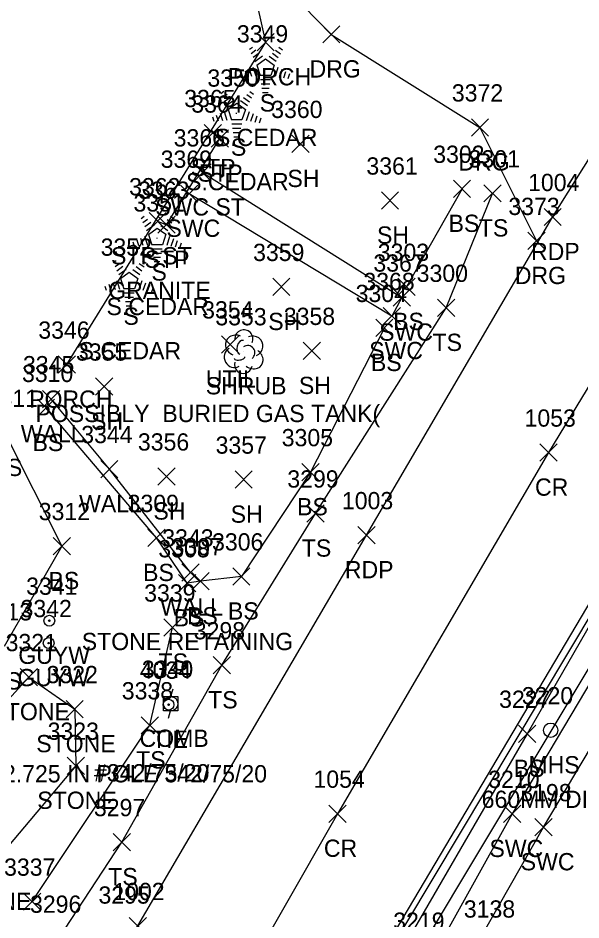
# Model space of a CAD drawing. Extents: x 1634209 to 1639641, y 608564 to 612258.
# Drawn here: x 1638888.9 to 1638954.2, y 610938 to 611042.5 of the extents above; entities that cross this region are included whole.
import ezdxf

# ---------------------------------------------------------------- set-up
doc = ezdxf.new("R2010")
doc.units = 0
for name, color, linetype in [('C_A', 7, 'Continuous'), ('C_C', 7, 'Continuous'), ('C_I', 7, 'Continuous'), ('CBP', 7, 'Continuous'), ('DCP', 7, 'Continuous'), ('L_A', 7, 'Continuous'), ('L_C', 7, 'Continuous'), ('L_I', 7, 'Continuous'), ('L_TIC', 7, 'Continuous'), ('LASF', 7, 'Continuous'), ('LBF', 7, 'Continuous'), ('LELB', 7, 'Continuous'), ('LSH', 7, 'Continuous'), ('LTC', 7, 'Continuous'), ('LW', 7, 'Continuous'), ('P_A', 7, 'Continuous'), ('P_I', 7, 'Continuous'), ('P_TIC', 7, 'Continuous'), ('PET', 7, 'Continuous'), ('PRC', 7, 'Continuous'), ('R_A', 7, 'Continuous'), ('R_I', 7, 'Continuous'), ('R_TIC', 7, 'Continuous'), ('RDG', 7, 'Continuous'), ('RSW', 7, 'Continuous'), ('U_A', 7, 'Continuous'), ('U_C', 7, 'Continuous'), ('U_I', 7, 'Continuous'), ('UDEFAULT', 7, 'Continuous'), ('UP', 7, 'Continuous'), ('UPGW', 7, 'Continuous'), ('USMH', 7, 'Continuous')]:
    doc.layers.add(name, color=color, linetype=linetype)

msp = doc.modelspace()

# ---------------------------------------------------------------- linework, layer by layer
at = {"layer": 'CBP'}
for radius in [0.625, 0.0833]:
    msp.add_circle((1638906.38, 610962.92), radius, dxfattribs=at)
at = {"layer": 'DCP'}
msp.add_lwpolyline([(1638930.73, 610932.22), (1638981.11, 611016.29)], dxfattribs=at)
at = {"layer": 'L_TIC'}
for points in [[(1638916.64, 611038.67), (1638918.64, 611040.67)], [(1638918.64, 611038.67), (1638916.64, 611040.67)], [(1638910.5, 611028.15), (1638912.5, 611030.15)], [(1638912.5, 611028.15), (1638910.5, 611030.15)], [(1638911.32, 611027.51), (1638913.32, 611029.51)], [(1638913.32, 611027.51), (1638911.32, 611029.51)], [(1638920.67, 611026.89), (1638922.67, 611028.89)], [(1638922.67, 611026.89), (1638920.67, 611028.89)], [(1638939.41, 611021.69), (1638941.41, 611023.69)], [(1638941.41, 611021.69), (1638939.41, 611023.69)], [(1638942.95, 611021.16), (1638944.95, 611023.16)], [(1638944.95, 611021.16), (1638942.95, 611023.16)], [(1638931.06, 611020.33), (1638933.06, 611022.33)], [(1638933.06, 611020.33), (1638931.06, 611022.33)], [(1638904.11, 611017.93), (1638906.11, 611019.93)], [(1638906.11, 611017.93), (1638904.11, 611019.93)], [(1638905.15, 611017.53), (1638907.15, 611019.53)], [(1638907.15, 611017.53), (1638905.15, 611019.53)], [(1638918.45, 611010.32), (1638920.45, 611012.32)], [(1638920.45, 611010.32), (1638918.45, 611012.32)], [(1638932.98, 611010.33), (1638934.98, 611012.33)], [(1638934.98, 611010.33), (1638932.98, 611012.33)], [(1638937.58, 611007.9), (1638939.58, 611009.9)], [(1638939.58, 611007.9), (1638937.58, 611009.9)], [(1638930.4, 611005.57), (1638932.4, 611007.57)], [(1638932.4, 611005.57), (1638930.4, 611007.57)], [(1638922, 611002.91), (1638924, 611004.91)], [(1638924, 611002.91), (1638922, 611004.91)], [(1638893.59, 611001.32), (1638895.59, 611003.32)], [(1638895.59, 611001.32), (1638893.59, 611003.32)], [(1638897.9, 610998.78), (1638899.9, 611000.78)], [(1638899.9, 610998.78), (1638897.9, 611000.78)], [(1638891.75, 610997.31), (1638893.75, 610999.31)], [(1638893.75, 610997.31), (1638891.75, 610999.31)], [(1638891.16, 610996.3), (1638893.16, 610998.3)], [(1638893.16, 610996.3), (1638891.16, 610998.3)], [(1638898.51, 610989.22), (1638900.51, 610991.22)], [(1638900.51, 610989.22), (1638898.51, 610991.22)], [(1638921.83, 610988.86), (1638923.83, 610990.86)], [(1638923.83, 610988.86), (1638921.83, 610990.86)], [(1638905.13, 610988.36), (1638907.13, 610990.36)], [(1638907.13, 610988.36), (1638905.13, 610990.36)], [(1638914.09, 610988), (1638916.09, 610990)], [(1638916.09, 610988), (1638914.09, 610990)], [(1638922.42, 610984.07), (1638924.42, 610986.07)], [(1638924.42, 610984.07), (1638922.42, 610986.07)], [(1638903.97, 610981.24), (1638905.97, 610983.24)], [(1638905.97, 610981.24), (1638903.97, 610983.24)], [(1638893.01, 610980.3), (1638895.01, 610982.3)], [(1638895.01, 610980.3), (1638893.01, 610982.3)], [(1638907.91, 610977.24), (1638909.91, 610979.24)], [(1638909.91, 610977.24), (1638907.91, 610979.24)], [(1638909.07, 610976.22), (1638911.07, 610978.22)], [(1638911.07, 610976.22), (1638909.07, 610978.22)], [(1638913.82, 610976.78), (1638915.82, 610978.78)], [(1638915.82, 610976.78), (1638913.82, 610978.78)], [(1638907.53, 610975.99), (1638909.53, 610977.99)], [(1638909.53, 610975.99), (1638907.53, 610977.99)], [(1638905.82, 610970.86), (1638907.82, 610972.86)], [(1638907.82, 610970.86), (1638905.82, 610972.86)], [(1638911.56, 610966.49), (1638913.56, 610968.49)], [(1638913.56, 610966.49), (1638911.56, 610968.49)], [(1638889.17, 610965.12), (1638891.17, 610967.12)], [(1638891.17, 610965.12), (1638889.17, 610967.12)], [(1638894.49, 610961.41), (1638896.49, 610963.41)], [(1638896.49, 610961.41), (1638894.49, 610963.41)], [(1638903.21, 610959.53), (1638905.21, 610961.53)], [(1638905.21, 610959.53), (1638903.21, 610961.53)], [(1638946.97, 610958.55), (1638948.97, 610960.55)], [(1638948.97, 610958.55), (1638946.97, 610960.55)], [(1638894.61, 610954.85), (1638896.61, 610956.85)], [(1638896.61, 610954.85), (1638894.61, 610956.85)], [(1638899.97, 610946), (1638901.97, 610948)], [(1638901.97, 610946), (1638899.97, 610948)], [(1638889.56, 610939.1), (1638891.56, 610941.1)], [(1638891.56, 610939.1), (1638889.56, 610941.1)]]:
    msp.add_lwpolyline(points, dxfattribs=at)
at = {"layer": 'LASF'}
msp.add_lwpolyline([(1638882.52, 610952.4), (1638880.6, 610955.65), (1638890.17, 610966.12), (1638895.49, 610962.41), (1638895.61, 610955.85), (1638885.71, 610944.15), (1638879.84, 610948.64)], dxfattribs=at)
at = {"layer": 'LBF'}
for points in [[(1638894.59, 611002.32), (1638917.64, 611039.67), (1638915.8, 611047.97)], [(1638905.11, 611018.93), (1638906.15, 611018.53), (1638912.32, 611028.51), (1638911.5, 611029.15)]]:
    msp.add_lwpolyline(points, dxfattribs=at)
at = {"layer": 'LELB'}
for points in [[(1638893.63, 610935.81), (1638900.97, 610947), (1638912.56, 610967.49), (1638923.42, 610985.07), (1638938.58, 611008.9), (1638943.95, 611022.16)], [(1638940.41, 611022.69), (1638933.98, 611011.33)], [(1638980.31, 611015.48), (1638967.73, 610993.79), (1638947.97, 610959.55), (1638931.37, 610930.97), (1638912.43, 610898.55), (1638893.71, 610864.41), (1638879.66, 610839.16)], [(1638931.4, 611006.57), (1638922.83, 610989.86), (1638914.82, 610977.78), (1638910.07, 610977.22), (1638908.53, 610976.99), (1638904.97, 610982.24), (1638892.16, 610997.3)], [(1638887.4, 610994.41), (1638894.01, 610981.3), (1638887.3, 610969.68), (1638874.48, 610974.16)], [(1638882.82, 610837.01), (1638905.5, 610879.25), (1638921.2, 610907.42), (1638935.13, 610933.84), (1638959.96, 610975.17)], [(1638890.56, 610940.1), (1638904.21, 610960.53), (1638906.82, 610971.86)]]:
    msp.add_lwpolyline(points, dxfattribs=at)
at = {"layer": 'LSH'}
msp.add_line((1638915.06, 611003.87), (1638915.06, 611003.87), dxfattribs=at)
msp.add_line((1638915.06, 611003.87), (1638915.06, 611003.87), dxfattribs=at)
msp.add_arc((1638915.11, 611005.3), 1.05, 335.5272, 180.9563, dxfattribs=at)
for centre, major_axis, ratio, start_param, end_param in [((1638914.27, 611004.54), (1.21, -0.51), 0.895232, 1.570796, 4.712389), ((1638916.1, 611004.45), (-1.14, -0.48), 0.949671, 1.570796, 4.712389), ((1638914.85, 611004.33), (-0.208, -0.792), 0.645439, 3.141593, 6.283185), ((1638915.56, 611003.7), (-0.5, 0.667), 0.989748, 3.141593, 6.283185), ((1638913.98, 611003.16), (0.58, -1.04), 0.959034, 3.141593, 6.283185), ((1638916.06, 611003.04), (-1.09, 0.79), 0.841452, 1.570796, 4.712389), ((1638915.06, 611002.37), (0.26, 1.06), 0.942809, 1.570796, 4.712389), ((1638914.6, 611003.12), (-0.625, -0.083), 0.423636, 0, 3.141593)]:
    msp.add_ellipse(centre, major_axis=major_axis, ratio=ratio, start_param=start_param, end_param=end_param, dxfattribs=at)
at = {"layer": 'LTC'}
for p, q in [((1638915.76, 611038.85), (1638916.12, 611039.11)), ((1638915.97, 611038.38), (1638916.5, 611038.77)), ((1638919.16, 611039.09), (1638919.58, 611038.79)), ((1638916.18, 611037.92), (1638916.89, 611038.43)), ((1638916.39, 611037.45), (1638917.27, 611038.09)), ((1638916.62, 611037), (1638917.63, 611037.73)), ((1638917.63, 611037.73), (1638918.62, 611037.01)), ((1638918.05, 611038.05), (1638918.86, 611037.46)), ((1638918.42, 611038.39), (1638919.1, 611037.9)), ((1638918.79, 611038.74), (1638919.34, 611038.34)), ((1638916.16, 611036.78), (1638916.49, 611035.76)), ((1638916.62, 611037), (1638917, 611035.8)), ((1638918.62, 611037.01), (1638918.23, 611035.8)), ((1638919.06, 611036.74), (1638918.72, 611035.7)), ((1638914.8, 611036.13), (1638914.95, 611035.66)), ((1638915.25, 611036.35), (1638915.46, 611035.69)), ((1638915.71, 611036.56), (1638915.98, 611035.73)), ((1638918.23, 611035.8), (1638917, 611035.8)), ((1638919.51, 611036.49), (1638919.22, 611035.6)), ((1638919.95, 611036.24), (1638919.71, 611035.51)), ((1638920.4, 611035.99), (1638920.21, 611035.41)), ((1638918.2, 611035.3), (1638917.05, 611035.3)), ((1638918.11, 611034.8), (1638917.12, 611034.8)), ((1638912.42, 611033.73), (1638912.78, 611033.98)), ((1638912.63, 611033.26), (1638913.16, 611033.65)), ((1638915.45, 611033.62), (1638916, 611033.22)), ((1638915.82, 611033.97), (1638916.24, 611033.66)), ((1638918.03, 611034.3), (1638917.2, 611034.3)), ((1638917.94, 611033.8), (1638917.27, 611033.8)), ((1638912.84, 611032.8), (1638913.55, 611033.31)), ((1638913.05, 611032.33), (1638913.93, 611032.97)), ((1638913.28, 611031.87), (1638914.29, 611032.61)), ((1638914.29, 611032.61), (1638915.28, 611031.88)), ((1638914.71, 611032.92), (1638915.52, 611032.33)), ((1638915.08, 611033.27), (1638915.76, 611032.78)), ((1638912.82, 611031.66), (1638913.15, 611030.64)), ((1638913.28, 611031.87), (1638913.66, 611030.68)), ((1638915.28, 611031.88), (1638914.89, 611030.68)), ((1638915.72, 611031.61), (1638915.38, 611030.57)), ((1638911.46, 611031.01), (1638911.61, 611030.54)), ((1638911.91, 611031.22), (1638912.12, 611030.57)), ((1638912.37, 611031.44), (1638912.64, 611030.6)), ((1638914.89, 611030.68), (1638913.66, 611030.68)), ((1638916.17, 611031.36), (1638915.88, 611030.48)), ((1638916.61, 611031.11), (1638916.37, 611030.38)), ((1638917.06, 611030.86), (1638916.87, 611030.29)), ((1638914.86, 611030.18), (1638913.71, 611030.18)), ((1638914.77, 611029.68), (1638913.78, 611029.68)), ((1638914.69, 611029.18), (1638913.86, 611029.18)), ((1638914.6, 611028.68), (1638913.93, 611028.68)), ((1638903.2, 611019.26), (1638903.55, 611019.52)), ((1638903.41, 611018.79), (1638903.94, 611019.18)), ((1638906.23, 611019.15), (1638906.77, 611018.75)), ((1638906.6, 611019.5), (1638907.02, 611019.2)), ((1638903.62, 611018.33), (1638904.32, 611018.84)), ((1638903.83, 611017.86), (1638904.71, 611018.5)), ((1638904.05, 611017.41), (1638905.06, 611018.14)), ((1638905.06, 611018.14), (1638906.06, 611017.42)), ((1638905.48, 611018.45), (1638906.29, 611017.87)), ((1638905.85, 611018.8), (1638906.53, 611018.31)), ((1638903.14, 611016.97), (1638903.41, 611016.14)), ((1638903.6, 611017.19), (1638903.93, 611016.17)), ((1638904.05, 611017.41), (1638904.44, 611016.21)), ((1638906.06, 611017.42), (1638905.67, 611016.21)), ((1638906.5, 611017.15), (1638906.16, 611016.11)), ((1638906.94, 611016.9), (1638906.65, 611016.01)), ((1638902.23, 611016.54), (1638902.38, 611016.07)), ((1638902.69, 611016.76), (1638902.9, 611016.1)), ((1638905.67, 611016.21), (1638904.44, 611016.21)), ((1638907.39, 611016.65), (1638907.15, 611015.92)), ((1638907.83, 611016.4), (1638907.64, 611015.82)), ((1638905.63, 611015.71), (1638904.49, 611015.71)), ((1638905.55, 611015.21), (1638904.56, 611015.21)), ((1638899.96, 611014.14), (1638900.31, 611014.39)), ((1638900.17, 611013.67), (1638900.7, 611014.05)), ((1638900.38, 611013.2), (1638901.08, 611013.72)), ((1638902.98, 611014.03), (1638903.53, 611013.63)), ((1638903.36, 611014.38), (1638903.77, 611014.07)), ((1638905.46, 611014.71), (1638904.63, 611014.71)), ((1638905.38, 611014.21), (1638904.7, 611014.21)), ((1638900.59, 611012.74), (1638901.46, 611013.38)), ((1638900.81, 611012.28), (1638901.82, 611013.02)), ((1638901.82, 611013.02), (1638902.82, 611012.29)), ((1638902.24, 611013.33), (1638903.05, 611012.74)), ((1638902.61, 611013.68), (1638903.29, 611013.19)), ((1638899.45, 611011.63), (1638899.66, 611010.98)), ((1638899.9, 611011.85), (1638900.17, 611011.01)), ((1638900.36, 611012.06), (1638900.69, 611011.05)), ((1638900.81, 611012.28), (1638901.2, 611011.09)), ((1638902.82, 611012.29), (1638902.43, 611011.09)), ((1638903.26, 611012.02), (1638902.92, 611010.98)), ((1638903.7, 611011.77), (1638903.41, 611010.89)), ((1638898.99, 611011.41), (1638899.14, 611010.95)), ((1638902.43, 611011.09), (1638901.2, 611011.09)), ((1638902.39, 611010.59), (1638901.25, 611010.59)), ((1638904.15, 611011.52), (1638903.91, 611010.79)), ((1638904.59, 611011.27), (1638904.4, 611010.7)), ((1638902.31, 611010.09), (1638901.32, 611010.09)), ((1638902.22, 611009.59), (1638901.39, 611009.59)), ((1638902.14, 611009.09), (1638901.46, 611009.09))]:
    msp.add_line(p, q, dxfattribs=at)
at = {"layer": 'LW'}
msp.add_lwpolyline([(1638908.91, 610978.24), (1638899.51, 610990.22), (1638892.75, 610998.31)], dxfattribs=at)
at = {"layer": 'P_TIC'}
for points in [[(1638949.92, 611018.42), (1638951.92, 611020.42)], [(1638951.92, 611018.42), (1638949.92, 611020.42)], [(1638949.44, 610991.13), (1638951.44, 610993.13)], [(1638951.44, 610991.13), (1638949.44, 610993.13)], [(1638928.33, 610981.56), (1638930.33, 610983.56)], [(1638930.33, 610981.56), (1638928.33, 610983.56)], [(1638924.96, 610949.29), (1638926.96, 610951.29)], [(1638926.96, 610949.29), (1638924.96, 610951.29)], [(1638901.82, 610936.28), (1638903.82, 610938.28)], [(1638903.82, 610936.28), (1638901.82, 610938.28)]]:
    msp.add_lwpolyline(points, dxfattribs=at)
at = {"layer": 'PET'}
for points in [[(1638854.83, 610853.22), (1638885.37, 610909), (1638902.82, 610937.28), (1638929.33, 610982.56), (1638950.92, 611019.42), (1638971.29, 611051.92), (1639000.04, 611096.96), (1639023.57, 611133.7), (1639039.12, 611159.19), (1639064.62, 611197.78), (1639080.51, 611223.3), (1639114.23, 611277.34), (1639131.17, 611302.28), (1639149.64, 611331.79), (1639176.42, 611372.35), (1639193.48, 611398.88), (1639220.96, 611441.47), (1639247.22, 611483.75)], [(1638878.4, 610839.82), (1638902.26, 610883.1), (1638925.76, 610925.06), (1638957.25, 610978.12), (1638978.73, 611014.12), (1639004.29, 611055.32), (1639040.97, 611112.28), (1639073.41, 611162.89), (1639072.72, 611163.46), (1639102.57, 611207.56), (1639124.27, 611240.99), (1639140.69, 611264.29), (1639156.2, 611287.4), (1639175.63, 611318.1), (1639189.77, 611341.61), (1639219.88, 611389.38), (1639245.26, 611428.04), (1639265.27, 611462.65)]]:
    msp.add_lwpolyline(points, dxfattribs=at)
at = {"layer": 'PRC'}
msp.add_lwpolyline([(1639250.46, 611462.84), (1639222.36, 611418.18), (1639195.34, 611376.28), (1639169.71, 611336.75), (1639147.17, 611302.78), (1639120.59, 611261.16), (1639092.55, 611217.83), (1639063.71, 611172.41), (1639032.46, 611123.7), (1639004.79, 611080.3), (1638977.88, 611037.27), (1638950.44, 610992.13), (1638925.96, 610950.29), (1638900.29, 610905.36), (1638879.75, 610869.2), (1638867.15, 610846.08)], dxfattribs=at)
at = {"layer": 'R_TIC'}
for points in [[(1638924.25, 611039.58), (1638926.25, 611041.58)], [(1638926.25, 611039.58), (1638924.25, 611041.58)], [(1638941.49, 611028.8), (1638943.49, 611030.8)], [(1638943.49, 611028.8), (1638941.49, 611030.8)], [(1638909.33, 611023.59), (1638911.33, 611025.59)], [(1638911.33, 611023.59), (1638909.33, 611025.59)], [(1638907.77, 611021.12), (1638909.77, 611023.12)], [(1638909.77, 611021.12), (1638907.77, 611023.12)], [(1638948.04, 611015.65), (1638950.04, 611017.65)], [(1638950.04, 611015.65), (1638948.04, 611017.65)], [(1638932.43, 611009.09), (1638934.43, 611011.09)], [(1638934.43, 611009.09), (1638932.43, 611011.09)], [(1638931.28, 611006.95), (1638933.28, 611008.95)], [(1638933.28, 611006.95), (1638931.28, 611008.95)], [(1638945.23, 610949.27), (1638947.23, 610951.27)], [(1638947.23, 610949.27), (1638945.23, 610951.27)], [(1638948.86, 610947.73), (1638950.86, 610949.73)], [(1638950.86, 610947.73), (1638948.86, 610949.73)]]:
    msp.add_lwpolyline(points, dxfattribs=at)
at = {"layer": 'RDG'}
msp.add_lwpolyline([(1638917.17, 611048.87), (1638925.25, 611040.58), (1638942.49, 611029.8), (1638949.04, 611016.65)], dxfattribs=at)
at = {"layer": 'RSW'}
for points in [[(1639042.52, 611106.87), (1639016.95, 611067.31), (1638996.03, 611033.02), (1638978.68, 611004.78), (1638963.33, 610979.05), (1638946.23, 610950.27), (1638931.64, 610924.09), (1638919.4, 610902.22), (1638904.83, 610875.98), (1638895.3, 610858.44), (1638883.54, 610836.57)], [(1638887.24, 610836.54), (1638902.8, 610864.3), (1638908.08, 610874.62), (1638910.81, 610879.12), (1638923.92, 610902.1), (1638938.05, 610928.02), (1638949.86, 610948.73), (1638968.01, 610979.25), (1638983.29, 611004.79), (1638997.34, 611027.92), (1639015.73, 611058.3), (1639044.74, 611103.21)], [(1638910.33, 611024.59), (1638933.43, 611010.09), (1638932.28, 611007.95), (1638908.77, 611022.12)]]:
    msp.add_lwpolyline(points, dxfattribs=at)
at = {"layer": 'UDEFAULT'}
for points in [[(1638912.53, 611003.66), (1638914.53, 611005.66)], [(1638914.53, 611003.66), (1638912.53, 611005.66)]]:
    msp.add_lwpolyline(points, dxfattribs=at)
at = {"layer": 'UP'}
for p, q in [((1638906.87, 610964.7), (1638906.62, 610963.87)), ((1638905.79, 610962.2), (1638905.79, 610963.87)), ((1638905.79, 610963.87), (1638907.46, 610963.87)), ((1638907.46, 610963.87), (1638907.46, 610962.2)), ((1638906.62, 610963.03), (1638906.62, 610963.03)), ((1638907.46, 610962.2), (1638905.79, 610962.2)), ((1638906.37, 610961.37), (1638906.62, 610962.2))]:
    msp.add_line(p, q, dxfattribs=at)
msp.add_circle((1638906.62, 610963.03), 0.833, dxfattribs=at)
at = {"layer": 'UPGW'}
for centre, radius in [((1638892.55, 610972.65), 0.625), ((1638892.55, 610972.65), 0.0833), ((1638892.47, 610970.06), 0.625), ((1638892.47, 610970.06), 0.0833)]:
    msp.add_circle(centre, radius, dxfattribs=at)
at = {"layer": 'USMH'}
for p, q in [((1638950.69, 610959.96), (1638950.69, 610959.96)), ((1638951.53, 610959.96), (1638951.53, 610959.96))]:
    msp.add_line(p, q, dxfattribs=at)
msp.add_circle((1638950.69, 610959.96), 0.833, dxfattribs=at)

# ---------------------------------------------------------------- texts
at = {"layer": 'C_A'}
msp.add_text('TIE', height=2, dxfattribs=at).set_placement((1638904.46, 610957.92))
at = {"layer": 'C_C'}
msp.add_text('32.725 IN POLE 342/75/20', height=2, dxfattribs=at).set_placement((1638885.68, 610953.92))
at = {"layer": 'C_I'}
msp.add_text('4034', height=2, dxfattribs=at).set_placement((1638903.04, 610965.92))
at = {"layer": 'L_A'}
for s, p in [('PORCH', (1638913.26, 611034.67)), ('S', (1638916.95, 611031.64)), ('S', (1638913.61, 611026.52)), ('STP', (1638908.95, 611024.15)), ('STP', (1638909.77, 611023.51)), ('SH', (1638920.16, 611022.89)), ('BS', (1638938.85, 611017.69)), ('TS', (1638942.36, 611017.16)), ('SH', (1638930.55, 611016.33)), ('STP ST', (1638899.7, 611013.93)), ('STP', (1638903.6, 611013.53)), ('S', (1638904.39, 611012.05)), ('S', (1638901.15, 611006.93)), ('SH', (1638917.94, 611006.32)), ('BS', (1638932.42, 611006.33)), ('TS', (1638936.99, 611003.9)), ('BS', (1638929.84, 611001.57)), ('SHRUB', (1638910.69, 610998.87)), ('SH', (1638921.49, 610998.91)), ('PORCH', (1638890.21, 610997.32)), ('SH', (1638897.39, 610994.78)), ('WALL', (1638889.24, 610993.31)), ('BS', (1638890.6, 610992.3)), ('BS', (1638885.84, 610989.41)), ('WALL', (1638896, 610985.22)), ('BS', (1638921.28, 610984.86)), ('SH', (1638904.62, 610984.36)), ('SH', (1638913.58, 610984)), ('TS', (1638921.83, 610980.07)), ('BS', (1638903.42, 610977.24)), ('BS', (1638892.45, 610976.3)), ('WALL', (1638905.4, 610973.24)), ('BS', (1638906.97, 610971.99)), ('BS', (1638908.51, 610972.22)), ('BS', (1638913.26, 610972.78)), ('TS', (1638905.22, 610966.86)), ('BS', (1638885.74, 610964.68)), ('TS', (1638910.97, 610962.49)), ('STONE', (1638885.72, 610961.12)), ('STONE', (1638891.03, 610957.41)), ('TS', (1638902.62, 610955.53)), ('BS', (1638946.41, 610954.55)), ('STONE', (1638891.15, 610950.85)), ('TS', (1638899.38, 610942)), ('STONE', (1638881.25, 610939.15))]:
    msp.add_text(s, height=2, dxfattribs=at).set_placement(p)
at = {"layer": 'L_C'}
for s, p in [('S.CEDAR', (1638911.75, 611027.64)), ('S.CEDAR', (1638908.41, 611022.52)), ('GRANITE', (1638899.38, 611009.93)), ('S.CEDAR', (1638899.18, 611008.05)), ('S.CEDAR', (1638895.94, 611002.93)), ('STONE RETAINING', (1638896.31, 610969.24))]:
    msp.add_text(s, height=2, dxfattribs=at).set_placement(p)
at = {"layer": 'L_I'}
for s, p in [('3349', (1638914.3, 611039.64)), ('3350', (1638910.88, 611034.52)), ('3365', (1638908.19, 611032.15)), ('3364', (1638909.01, 611031.51)), ('3360', (1638918.28, 611030.89)), ('3302', (1638937.07, 611025.69)), ('3361', (1638929.32, 611024.33)), ('3301', (1638941.18, 611025.16)), ('3362', (1638901.8, 611021.93)), ('3363', (1638902.84, 611021.53)), ('3351', (1638902.31, 611020.05)), ('3352', (1638898.5, 611014.93)), ('3359', (1638916.18, 611014.32)), ('3303', (1638930.64, 611014.33)), ('3300', (1638935.15, 611011.9)), ('3304', (1638928.07, 611009.57)), ('3353', (1638911.8, 611006.87)), ('3358', (1638919.74, 611006.91)), ('3346', (1638891.27, 611005.32)), ('3355', (1638895.64, 611002.78)), ('3345', (1638889.49, 611001.31)), ('3310', (1638889.38, 611000.3)), ('3311', (1638885.28, 610997.41)), ('3344', (1638896.25, 610993.22)), ('3305', (1638919.5, 610992.86)), ('3356', (1638902.82, 610992.36)), ('3357', (1638911.83, 610992)), ('3299', (1638920.15, 610988.07)), ('3309', (1638901.63, 610985.24)), ('3312', (1638891.32, 610984.3)), ('3343', (1638905.65, 610981.24)), ('3306', (1638911.42, 610980.78)), ('3308', (1638905.19, 610979.99)), ('3307', (1638906.73, 610980.22)), ('3339', (1638903.55, 610974.86)), ('3313', (1638884.6, 610972.68)), ('3298', (1638909.3, 610970.49)), ('3321', (1638887.48, 610969.12)), ('3322', (1638892.23, 610965.41)), ('3338', (1638900.95, 610963.53)), ('3227', (1638944.71, 610962.55)), ('3323', (1638892.35, 610958.85)), ('3297', (1638897.72, 610950)), ('3337', (1638887.3, 610943.1)), ('3296', (1638890.31, 610938.81)), ('3219', (1638932.43, 610936.84))]:
    msp.add_text(s, height=2, dxfattribs=at).set_placement(p)
at = {"layer": 'LTC'}
for p in [(1638917.51, 611036.75), (1638914.17, 611031.62), (1638904.95, 611017.16), (1638901.7, 611012.03)]:
    msp.add_text('.', height=1.04, rotation=270, dxfattribs=at).set_placement(p)
at = {"layer": 'P_A'}
for s, p in [('RDP', (1638948.41, 611014.42)), ('CR', (1638948.87, 610987.13)), ('RDP', (1638926.82, 610977.56)), ('CR', (1638924.39, 610945.29))]:
    msp.add_text(s, height=2, dxfattribs=at).set_placement(p)
at = {"layer": 'P_I'}
for s, p in [('1004', (1638948.07, 611022.42)), ('1053', (1638947.66, 610995.13)), ('1003', (1638926.48, 610985.56)), ('1054', (1638923.18, 610953.29)), ('1002', (1638899.97, 610940.28))]:
    msp.add_text(s, height=2, dxfattribs=at).set_placement(p)
at = {"layer": 'R_A'}
for s, p in [('DRG', (1638922.73, 611035.58)), ('DRG', (1638939.98, 611024.8)), ('SWC ST', (1638904.83, 611019.59)), ('SWC', (1638906.13, 611017.12)), ('DRG', (1638946.53, 611011.65)), ('SWC', (1638930.8, 611005.09)), ('SWC', (1638929.64, 611002.95)), ('SWC', (1638943.59, 610945.27)), ('SWC', (1638947.22, 610943.73))]:
    msp.add_text(s, height=2, dxfattribs=at).set_placement(p)
at = {"layer": 'R_I'}
for s, p in [('3372', (1638939.23, 611032.8)), ('3366', (1638906.97, 611027.59)), ('3369', (1638905.46, 611025.12)), ('3373', (1638945.78, 611019.65)), ('3367', (1638930.13, 611013.09)), ('3368', (1638928.97, 611010.95)), ('3210', (1638943.45, 610953.27)), ('3198', (1638947.17, 610951.73)), ('3295', (1638898.25, 610939.87)), ('3138', (1638940.62, 610938.25))]:
    msp.add_text(s, height=2, dxfattribs=at).set_placement(p)
at = {"layer": 'U_A'}
for s, p in [('UTIL', (1638910.7, 610999.66)), ('GUYW', (1638888.95, 610967.65)), ('GUYW', (1638888.86, 610965.06)), ('COMB', (1638903.01, 610958.03)), ('MHS', (1638948.11, 610954.96))]:
    msp.add_text(s, height=2, dxfattribs=at).set_placement(p)
at = {"layer": 'U_C'}
for s, p in [('POSSIBLY  BURIED GAS TANK(', (1638890.94, 610995.66)), ('#342/75/20', (1638897.73, 610954.03)), ('660MM DIA', (1638942.69, 610950.96))]:
    msp.add_text(s, height=2, dxfattribs=at).set_placement(p)
at = {"layer": 'U_I'}
for s, p in [('3354', (1638910.27, 611007.66)), ('3341', (1638889.86, 610975.65)), ('3342', (1638889.21, 610973.06)), ('3340', (1638903.28, 610966.03)), ('3220', (1638947.35, 610962.96))]:
    msp.add_text(s, height=2, dxfattribs=at).set_placement(p)

doc.saveas('drawing.dxf')
